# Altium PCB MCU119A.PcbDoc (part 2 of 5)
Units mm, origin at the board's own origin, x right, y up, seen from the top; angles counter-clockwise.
Board outline 58.62 x 144.37 mm, 6 copper layers (Top Signal, GND, Middle Signal, PWR, GND2, Bottom Signal), stack 1.566 mm thick; 316 components, 238 nets, 1210 pads, 1064 vias.
Unrouted connection lines stored in the file: 59.
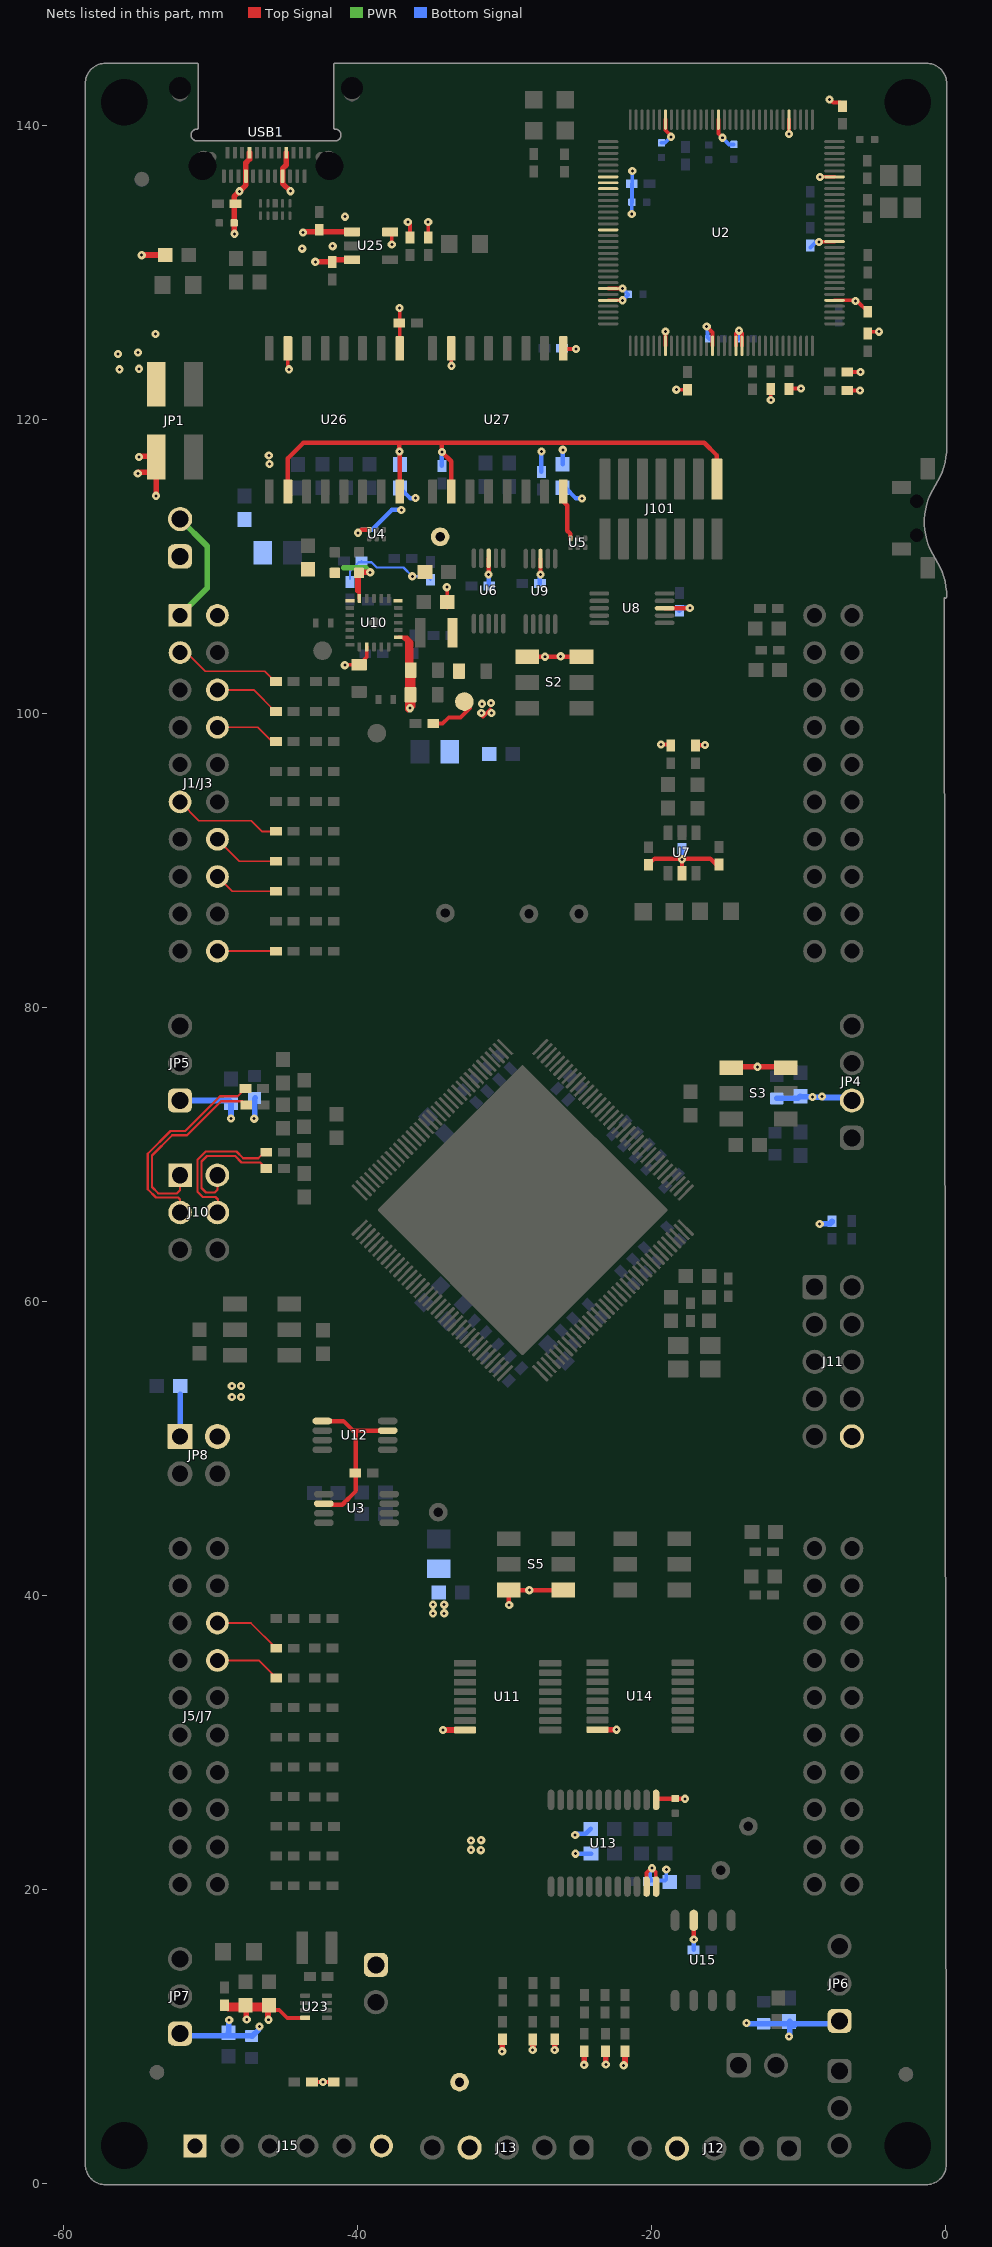
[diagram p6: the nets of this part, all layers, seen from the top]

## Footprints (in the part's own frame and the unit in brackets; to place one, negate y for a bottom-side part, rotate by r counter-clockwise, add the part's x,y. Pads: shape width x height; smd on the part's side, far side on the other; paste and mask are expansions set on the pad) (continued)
PDT0128A [mm] "Thin QFP, 128-Leads, Body 14x14mm, Pitch 0.4mm"
  oval 1.4x0.2 smd: 1(-7.7,6.2) 2(-7.7,5.8) 3(-7.7,5.4) 4(-7.7,5) 5(-7.7,4.6) 6(-7.7,4.2) 7(-7.7,3.8) 8(-7.7,3.4) 9(-7.7,3) 10(-7.7,2.6) 11(-7.7,2.2) 12(-7.7,1.8) 13(-7.7,1.4) 14(-7.7,1) 15(-7.7,0.6) 16(-7.7,0.2) 17(-7.7,-0.2) 18(-7.7,-0.6) 19(-7.7,-1) 20(-7.7,-1.4) 21(-7.7,-1.8) 22(-7.7,-2.2) 23(-7.7,-2.6) 24(-7.7,-3) 25(-7.7,-3.4) 26(-7.7,-3.8) 27(-7.7,-4.2) 28(-7.7,-4.6) 29(-7.7,-5) 30(-7.7,-5.4) 31(-7.7,-5.8) 32(-7.7,-6.2) 65(7.7,-6.2) 66(7.7,-5.8) 67(7.7,-5.4) 68(7.7,-5) 69(7.7,-4.6) 70(7.7,-4.2) 71(7.7,-3.8) 72(7.7,-3.4) 73(7.7,-3) 74(7.7,-2.6) 75(7.7,-2.2) 76(7.7,-1.8) 77(7.7,-1.4) 78(7.7,-1) 79(7.7,-0.6) 80(7.7,-0.2) 81(7.7,0.2) 82(7.7,0.6) 83(7.7,1) 84(7.7,1.4) 85(7.7,1.8) 86(7.7,2.2) 87(7.7,2.6) 88(7.7,3) 89(7.7,3.4) 90(7.7,3.8) 91(7.7,4.2) 92(7.7,4.6) 93(7.7,5) 94(7.7,5.4) 95(7.7,5.8) 96(7.7,6.2)
  oval 0.2x1.4 smd: 33(-6.2,-7.7) 34(-5.8,-7.7) 35(-5.4,-7.7) 36(-5,-7.7) 37(-4.6,-7.7) 38(-4.2,-7.7) 39(-3.8,-7.7) 40(-3.4,-7.7) 41(-3,-7.7) 42(-2.6,-7.7) 43(-2.2,-7.7) 44(-1.8,-7.7) 45(-1.4,-7.7) 46(-1,-7.7) 47(-0.6,-7.7) 48(-0.2,-7.7) 49(0.2,-7.7) 50(0.6,-7.7) 51(1,-7.7) 52(1.4,-7.7) 53(1.8,-7.7) 54(2.2,-7.7) 55(2.6,-7.7) 56(3,-7.7) 57(3.4,-7.7) 58(3.8,-7.7) 59(4.2,-7.7) 60(4.6,-7.7) 61(5,-7.7) 62(5.4,-7.7) 63(5.8,-7.7) 64(6.2,-7.7) 97(6.2,7.7) 98(5.8,7.7) 99(5.4,7.7) 100(5,7.7) 101(4.6,7.7) 102(4.2,7.7) 103(3.8,7.7) 104(3.4,7.7) 105(3,7.7) 106(2.6,7.7) 107(2.2,7.7) 108(1.8,7.7) 109(1.4,7.7) 110(1,7.7) 111(0.6,7.7) 112(0.2,7.7) 113(-0.2,7.7) 114(-0.6,7.7) 115(-1,7.7) 116(-1.4,7.7) 117(-1.8,7.7) 118(-2.2,7.7) 119(-2.6,7.7) 120(-3,7.7) 121(-3.4,7.7) 122(-3.8,7.7) 123(-4.2,7.7) 124(-4.6,7.7) 125(-5,7.7) 126(-5.4,7.7) 127(-5.8,7.7) 128(-6.2,7.7)
  silkscreen extent -7.7,-6.3 6.3,6.99, body extent -8,-8 8,8, height 1.07
PW0016A-MFG [mm]
  rrect22% 1.5x0.45 smd: 1(-2.9,2.275) 2(-2.9,1.625) 3(-2.9,0.975) 4(-2.9,0.325) 5(-2.9,-0.325) 6(-2.9,-0.975) 7(-2.9,-1.625) 8(-2.9,-2.275) 9(2.9,-2.275) 10(2.9,-1.625) 11(2.9,-0.975) 12(2.9,-0.325) 13(2.9,0.325) 14(2.9,0.975) 15(2.9,1.625) 16(2.9,2.275)
  silkscreen extent -4.38,-2.55 1.78,2.55, body extent -3.75,-2.8 3.75,2.8, height 0.25
PW0024A_N [mm] "TSOP, 24-Leads, Body 7.8x4.4mm, Pitch 0.65mm, IPC Medium Density"
  oval 1.4x0.45 smd: 1(-2.95,3.575) 2(-2.95,2.925) 3(-2.95,2.275) 4(-2.95,1.625) 5(-2.95,0.975) 6(-2.95,0.325) 7(-2.95,-0.325) 8(-2.95,-0.975) 9(-2.95,-1.625) 10(-2.95,-2.275) 11(-2.95,-2.925) 12(-2.95,-3.575) 13(2.95,-3.575) 14(2.95,-2.925) 15(2.95,-2.275) 16(2.95,-1.625) 17(2.95,-0.975) 18(2.95,-0.325) 19(2.95,0.325) 20(2.95,0.975) 21(2.95,1.625) 22(2.95,2.275) 23(2.95,2.925) 24(2.95,3.575)
  silkscreen extent -3.51,-3.95 1.6,4.04, body extent -3.21,-3.9 3.21,3.9, height 1
RAY0024B-MFG [mm]
  rrect40% 0.625x0.25 smd paste+0 mask+0: 1(-1.637,1.5) 7(-1.637,-1.5) 13(1.637,-1.5) 19(1.637,1.5)
  rrect40% 0.6x0.25 smd paste+0 mask+0: 2(-1.65,1) 3(-1.65,0.5) 5(-1.65,-0.5) 6(-1.65,-1) 14(1.65,-1) 15(1.65,-0.5) 17(1.65,0.5) 18(1.65,1)
  rrect40% 0.6x0.25 smd paste+0 mask-1000: 4(-1.65,0) 16(1.65,0)
  rrect40% 0.25x0.6 smd paste+0 mask+0: 8(-1,-1.65) 9(-0.5,-1.65) 10(0,-1.65) 11(0.5,-1.65) 12(1,-1.65) 20(1,1.65) 21(0.5,1.65) 22(0,1.65) 23(-0.5,1.65) 24(-1,1.65)
  round 0.777 smd paste-1000 mask+0: ""(0.037,-0.003)
  Top Signal region: -1.95,0.075 -1.943,0.1 -1.925,0.118 -1.9,0.125 -1.9,0.125 -1.4,0.125 -1.378,0.12 -1.361,0.106 -1.361,0.106 -1.344,0.092 -1.322,0.088 -1.322,0.088 -0.426,0.088 -0.406,0.091 -0.39,0.102 -0.379,0.118 -0.375,0.138 -0.376,0.138 -0.376,0.601 -0.369,0.626 -0.35,0.644 -0.325,0.651 -0.325,0.651 0.455,0.651 0.48,0.644 0.499,0.626 0.505,0.601 0.505,0.601 0.506,0.1 0.509,0.081 0.52,0.065 0.536,0.054 0.556,0.05 0.556,0.05 1.303,0.05 1.324,0.055 1.342,0.068 1.352,0.088 1.352,0.088 1.362,0.107 1.379,0.12 1.4,0.125 1.4,0.125 1.9,0.125 1.925,0.118 1.943,0.1 1.95,0.075 1.95,0.075 1.95,-0.075 1.943,-0.1 1.925,-0.118 1.9,-0.125 1.9,-0.125 0.556,-0.125 0.536,-0.129 0.52,-0.14 0.509,-0.156 0.506,-0.175 0.506,-0.175 0.506,-0.601 0.499,-0.626 0.481,-0.644 0.456,-0.651 0.455,-0.651 -0.326,-0.651 -0.35,-0.644 -0.369,-0.626 -0.375,-0.601 -0.375,-0.601 -0.376,-0.137 -0.379,-0.118 -0.39,-0.102 -0.406,-0.091 -0.425,-0.087 -0.426,-0.087 -1.322,-0.087 -1.344,-0.092 -1.361,-0.106 -1.361,-0.106 -1.378,-0.12 -1.4,-0.125 -1.4,-0.125 -1.9,-0.125 -1.925,-0.118 -1.943,-0.1 -1.95,-0.075 -1.95,-0.075
  silkscreen extent -2.62,-2.17 2.18,2.18, body extent -1.75,-1.75 1.75,1.75, height 1
RFS0144A-MFG [mm]
  rrect50% 1.45x0.2 smd paste+0 mask+0: 1(-8.7,7) 2(-8.7,6.6) 3(-8.7,6.2) 4(-8.7,5.8) 5(-8.7,5.4) 6(-8.7,5) 7(-8.7,4.6) 8(-8.7,4.2) 9(-8.7,3.8) 10(-8.7,3.4) 11(-8.7,3) 12(-8.7,2.6) 13(-8.7,2.2) 14(-8.7,1.8) 15(-8.7,1.4) 16(-8.7,1) 17(-8.7,0.6) 18(-8.7,0.2) 19(-8.7,-0.2) 20(-8.7,-0.6) 21(-8.7,-1) 22(-8.7,-1.4) 23(-8.7,-1.8) 24(-8.7,-2.2) 25(-8.7,-2.6) 26(-8.7,-3) 27(-8.7,-3.4) 28(-8.7,-3.8) 29(-8.7,-4.2) 30(-8.7,-4.6) 31(-8.7,-5) 32(-8.7,-5.4) 33(-8.7,-5.8) 34(-8.7,-6.2) 35(-8.7,-6.6) 36(-8.7,-7) 73(8.7,-7) 74(8.7,-6.6) 75(8.7,-6.2) 76(8.7,-5.8) 77(8.7,-5.4) 78(8.7,-5) 79(8.7,-4.6) 80(8.7,-4.2) 81(8.7,-3.8) 82(8.7,-3.4) 83(8.7,-3) 84(8.7,-2.6) 85(8.7,-2.2) 86(8.7,-1.8) 87(8.7,-1.4) 88(8.7,-1) 89(8.7,-0.6) 90(8.7,-0.2) 91(8.7,0.2) 92(8.7,0.6) 93(8.7,1) 94(8.7,1.4) 95(8.7,1.8) 96(8.7,2.2) 97(8.7,2.6) 98(8.7,3) 99(8.7,3.4) 100(8.7,3.8) 101(8.7,4.2) 102(8.7,4.6) 103(8.7,5) 104(8.7,5.4) 105(8.7,5.8) 106(8.7,6.2) 107(8.7,6.6) 108(8.7,7)
  rrect50% 0.2x1.45 smd paste+0 mask+0: 37(-7,-8.7) 38(-6.6,-8.7) 39(-6.2,-8.7) 40(-5.8,-8.7) 41(-5.4,-8.7) 42(-5,-8.7) 43(-4.6,-8.7) 44(-4.2,-8.7) 45(-3.8,-8.7) 46(-3.4,-8.7) 47(-3,-8.7) 48(-2.6,-8.7) 49(-2.2,-8.7) 50(-1.8,-8.7) 51(-1.4,-8.7) 52(-1,-8.7) 53(-0.6,-8.7) 54(-0.2,-8.7) 55(0.2,-8.7) 56(0.6,-8.7) 57(1,-8.7) 58(1.4,-8.7) 59(1.8,-8.7) 60(2.2,-8.7) 61(2.6,-8.7) 62(3,-8.7) 63(3.4,-8.7) 64(3.8,-8.7) 65(4.2,-8.7) 66(4.6,-8.7) 67(5,-8.7) 68(5.4,-8.7) 69(5.8,-8.7) 70(6.2,-8.7) 71(6.6,-8.7) 72(7,-8.7) 109(7,8.7) 110(6.6,8.7) 111(6.2,8.7) 112(5.8,8.7) 113(5.4,8.7) 114(5,8.7) 115(4.6,8.7) 116(4.2,8.7) 117(3.8,8.7) 118(3.4,8.7) 119(3,8.7) 120(2.6,8.7) 121(2.2,8.7) 122(1.8,8.7) 123(1.4,8.7) 124(1,8.7) 125(0.6,8.7) 126(0.2,8.7) 127(-0.2,8.7) 128(-0.6,8.7) 129(-1,8.7) 130(-1.4,8.7) 131(-1.8,8.7) 132(-2.2,8.7) 133(-2.6,8.7) 134(-3,8.7) 135(-3.4,8.7) 136(-3.8,8.7) 137(-4.2,8.7) 138(-4.6,8.7) 139(-5,8.7) 140(-5.4,8.7) 141(-5.8,8.7) 142(-6.2,8.7) 143(-6.6,8.7) 144(-7,8.7)
  rrect1% 14x14 smd paste-1000 mask-1000: 145(0,0)
  silkscreen extent -8.82,-8.05 8.05,8.05, body extent -9.53,-9.53 9.53,9.53, height 0.25
Samtec_TSM-102-01-x-DV [mm] "Header, 2.54mm, 2x2, SMT"
  rect 3.048x1.27 smd: 1(-2.475,-1.27) 2(2.475,-1.27) 3(-2.475,1.27) 4(2.475,1.27)
  silkscreen extent -1.75,-2.63 1.65,2.54, body extent -3.85,-2.54 3.85,2.54, height 9.65
SW_1188E [mm] "SMD, 4-Leads, Body 7.8x3.5mm"
  rrect10% 1x1.45 smd: 1(-1.1,3.375) 2(-1.1,-3.375)
  rrect11% 1.3x0.9 smd: 3(0.7,2.1) 4(0.7,-2.1)
  round 0 hole 0.9 unplated: ""(-0.35,1.15) ""(-0.35,-1.15)
  silkscreen extent -1.98,-2.28 0.95,2.28, body extent -2.55,-3.9 1.05,3.9, height 3.5
SW_CAS-220TA [mm] "COPAL ELECTRONICS"
  rect 1.6x1 smd: 1(-1.85,1.75) 2(-1.85,0) 3(-1.85,-1.75) 4(1.85,1.75) 5(1.85,0) 6(1.85,-1.75)
  silkscreen extent -2.11,-2.9 2,3.58, body extent -2.1,-2.85 2.1,2.85, height 2.51
SW_CAS-D20TA [mm] "SMD, 6-Leads, Body 5.4x3.9mm, Pitch 1.75mm"
  rect 1.6x1 smd: 1(-1.85,1.75) 2(-1.85,0) 3(-1.85,-1.75) 4(1.85,1.75) 5(1.85,0) 6(1.85,-1.75)
  silkscreen extent -1.95,-2.7 1.95,2.9, body extent -2.1,-2.7 2.1,2.7, height 2.5
TFM252012 [mm] "SMD, 2-Leads, Body 2.5x2mm"
  rect 0.7x2 smd: 1(-1.1,0) 2(1.1,0)
  silkscreen extent -0.45,-1.1 0.45,1.1, body extent -1.35,-1.1 1.35,1.1, height 1.2
TI_Stacked_Overlay_Medium [mm]
  silkscreen extent -14.62,-3.44 14.62,3.42
TI_Symbol_Overlay_Small [mm]
  silkscreen extent -2.3,-2.23 2.3,2.24
TP_50MIL-25MILHOLE#1 [mm]
  round 1.27 hole 0.635: 1(0,0)
TP_50MIL-25MILHOLE#2 [mm]
  round 1.27 smd paste-2: 1(0,0)
TP_50MIL-25MILHOLE#3 [mm]
  round 1.27 smd paste-5.08: 1(0,0)
WEEE_Minimum [mm] "WEEElie bin"
  silkscreen extent -2.42,-4.38 2.52,2.65
WL-SMCW_Green_0805 [mm] "SMD, 2-Leads, Body 2x1.25mm"
  rect 1.1x1.2 smd: 1(-1.05,0) 2(1.05,0)
  silkscreen extent -2.39,-1.1 1.5,1.1, body extent -1,-0.62 1,0.63, height 0.7
WL-SMCW_RED_0805 [mm] "SMD, 2-Leads, Body 1.6x0.8mm"
  rect 1.1x1.2 smd: 1(-1.05,0) 2(1.05,0)
  silkscreen extent -2.4,-1.1 1.5,1.1, body extent -1,-0.62 1,0.63, height 0.7
Wurth_60900213421 [mil] "Shunt, 2.54mm, Black"
  round 1 on Mech3: 0(0,0)
  body extent -98,-48 98,48, height 338
WURTH_61300211121 [mm] "Header, 2.54mm, 2x1, TH"
  rrect50% 1.65x1.65 hole 1.15: 1(-1.27,0)
  round 1.65 hole 1.15: 2(1.27,0)
  body extent -2.54,-1.27 2.54,1.27, height 8.54
WURTH_61300311121 [mm] "Header, 2.54mm, 3x1, TH"
  rrect50% 1.65x1.65 hole 1.15: 1(-2.54,0)
  round 1.65 hole 1.15: 2(0,0) 3(2.54,0)
  body extent -3.81,-1.27 3.81,1.27, height 8.54
WURTH_61300411121 [mm] "Header, 2.54mm, 4x1, TH"
  rrect50% 1.65x1.65 hole 1.15: 1(-3.81,0)
  round 1.65 hole 1.15: 2(-1.27,0) 3(1.27,0) 4(3.81,0)
  body extent -5.08,-1.27 5.08,1.27, height 8.54
Wurth_61300511121 [mm] "Header, 2.54mm, 5x1, TH"
  rrect50% 1.65x1.65 hole 1.1: 1(-5.08,0)
  round 1.65 hole 1.1: 2(-2.54,0) 3(0,0) 4(2.54,0) 5(5.08,0)
  body extent -6.35,-1.27 6.35,1.27, height 8.54
Wurth_61300621121 [mm] "Header, 2.54mm, 3x2, TH"
  rect 1.6x1.6 hole 1.1: 1(-1.27,2.54)
  round 1.6 hole 1.1: 2(1.27,2.54) 3(-1.27,0) 4(1.27,0) 5(-1.27,-2.54) 6(1.27,-2.54)
  silkscreen extent -2.8,-3.82 2.54,3.8, body extent -2.54,-3.82 2.54,3.8, height 7.27
WURTH_61301021121 [mm] "Header, 2.54mm, 5x2, TH"
  rrect25% 1.65x1.65 hole 1.15: 1(-5.08,-1.27)
  round 1.65 hole 1.15: 2(-5.08,1.27) 3(-2.54,-1.27) 4(-2.54,1.27) 5(0,-1.27) 6(0,1.27) 7(2.54,-1.27) 8(2.54,1.27) 9(5.08,-1.27) 10(5.08,1.27)
  silkscreen extent -6.35,-2.9 6.35,2.54, body extent -6.35,-2.54 6.35,2.54, height 8.54

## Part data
C1 C2 C3 C4 C5 C12 C16 C17 C18 C55 C56 C57 C58 C63 C66 C67 C68 C69 C70 C71 C72 C73 C97 C98 C99 C100 C101 C102 C103 C104 C105 C106 C128 C129 C130 C132 C133: library part CMP-0006228-2, "CAP, CERM, 0.1 uF, 16 V, +/- 10%, X7R, 0402", Cap_Case=0402, Manufacturer="Wurth Elektronik", Supplier Part Number 1=732-7532-1-ND, TempCo=X7R, Tolerance_%=10%, Value1=Unknown, Value2=16V, ValueDisplayed=0.1uF
C6 C7 C8 C9 C10 C11 C23: library part CMP-0006231-2, "CAP, CERM, 1000 pF, 50 V, +/- 10%, X7R, 0402", Cap_Case=0402, Manufacturer="Wurth Elektronik", Supplier Part Number 1=732-7556-1-ND, TempCo=X7R, Tolerance_%=10%, Value1=Unknown, Value2=50V, ValueDisplayed=1000pF
C13 C14: library part CMP-0007341-5, "CAP, CERM, 4.7 uF, 16 V, +/- 10%, X5R, 0603", Cap_Case=0603, Manufacturer=MuRata, PartNumber=GRM188R61C475KAAJ, Supplier Part Number 1=490-10481-1-ND, TempCo=X5R, Tolerance_%=10%, Value1=Unknown, Value2=16V, ValueDisplayed=2.2uF
C15 C126 C127: library part CMP-0078623-1, "CAP, CERM, 10 ¦ÌF, 10 V,+/- 20%, X5R, 0402", Cap_Case=0402_080, Manufacturer=AVX, Supplier Part Number 1=478-10052-1-ND, TempCo=X5R, Tolerance_%=20%, Value2=10V, ValueDisplayed=10¦ÌF
C19 C20: library part CMP-0006239-2, "CAP, CERM, 12 pF, 25 V, +/- 5%, C0G/NP0, AEC-Q200 Grade 1, 0402", Cap_Case=0402, Manufacturer=Kemet, Supplier Part Number 1=399-6829-1-ND, TempCo=C0G/NP0, Tolerance_%=5%, Value1=Unknown, Value2=25V, ValueDisplayed=12pF
C21 C137 C138 C143 C145: library part CMP-0090362-1, "0.1¦ÌF ¡À10% 10V Ceramic Capacitor X7R 0402 (1005 Metric)", Digikey Part Number=732-7513-1-ND, Manufacturer="Wurth Electronics", Mouser Part Number=710-885012205018, Operating Temperature Range="-55¡ãC to +125¡ãC", TempCo=15%, Temperature Characteristic=X7R, Tolerance_%=10%, ValueDisplayed=100000pF
C22 C51 C75 C77 C79 C82 C84 C88 C91: library part CMP-0006862-5, "CAP, CERM, 0.1 uF, 10 V, +/- 10%, X7R, 0603", Cap_Case=0603, Manufacturer=Kemet, Supplier Part Number 1=399-1095-1-ND, TempCo=X7R, Tolerance_%=10%, Value1=Unknown, Value2=10V, ValueDisplayed=0.1uF
C24 C25: library part CMP-0006920-4, "CAP, CERM, 1000 pF, 50 V, +/- 5%, C0G/NP0, 0603", Cap_Case=0603, Manufacturer=Kemet, PartNumber=C0603C331J5GACTU, Supplier Part Number 1=399-1068-1-ND, TempCo=C0G/NP0, Tolerance_%=5%, Value1=Unknown, Value2=50V, ValueDisplayed=330pF
C26 C27 C30 C31 C33 C34 C35 C36 C37 C38 C39 C40 C42 C43 C45 C46 C47 C48 C49 C50: library part CMP-0006456-2, "CAP, CERM, 330 pF, 50 V, +/- 5%, C0G/NP0, 0402", Cap_Case=0402, Manufacturer=MuRata, Supplier Part Number 1=490-1295-1-ND, TempCo=C0G/NP0, Tolerance_%=5%, Value1=Unknown, Value2=50V, ValueDisplayed=330pF
C28: library part CMP-0123381-1, "Ceramic Capacitor for Automotive 200pF ¡À1% 50VDC C0G 0402 Paper T/R", Manufacturer=Murata, Operating Temperature Range="-55¡ãC to +125¡ãC", TempCo=30ppm/¡ãC, Temperature Characteristic=C0G, Tolerance_%=0.01%, ValueDisplayed=200pF
C29 C32 C41 C44: library part CMP-0006920-4, "CAP, CERM, 2200 pF, 50 V, +/- 5%, X7R, 0402", Cap_Case=0603, Manufacturer=Kemet, PartNumber=C0603C331J5GACTU, Supplier Part Number 1=399-1068-1-ND, TempCo=C0G/NP0, Tolerance_%=5%, Value1=Unknown, Value2=50V, ValueDisplayed=330pF
C52: library part CMP-0006871-4, "CAP, CERM, 1 uF, 6.3 V, +80/-20%, Y5V, 0603", Cap_Case=0603, Manufacturer=Kemet, Supplier Part Number 1=399-3217-1-ND, TempCo=Y5V, Tolerance_%=80%, Value1=Unknown, Value2=6.3V, ValueDisplayed=1uF
C53: library part CMP-0006907-5, "CAP, CERM, 2.2 uF, 6.3 V, +/- 10%, X5R, 0603", Cap_Case=0603, Manufacturer=Kemet, Supplier Part Number 1=399-3362-1-ND, TempCo=X5R, Tolerance_%=10%, Value1=Unknown, Value2=6.3V, ValueDisplayed=2.2uF
C54 C59: library part CMP-0086225-1, "CAP, CERM, 10 ¦ÌF, 16 V,+/- 10%, X5R, 0603", Cap_Case=0603, Manufacturer=MuRata, Supplier Part Number 1=490-10728-1-ND, TempCo=X5R, Tolerance_%=10%, Value2=16V, ValueDisplayed=10¦ÌF
C60 C61 C62 C64 C65: library part CMP-0006825-5, "CAP, CERM, 2.2 uF, 16 V, +/- 20%, X5R, 0603", Cap_Case=0603, Manufacturer="Wurth Elektronik", Supplier Part Number 1=732-7915-1-ND, TempCo=X5R, Tolerance_%=20%, Value1=Unknown, Value2=16V, ValueDisplayed=2.2uF
C74 C76 C78 C81 C83: library part CMP-0092309-1, "Cap Ceramic 10uF 10V X5R 10% SMD 0603 85C Paper T/R", Digikey Part Number=311-1782-1-ND, Manufacturer=YAGEO, Mouser Part Number=603-CC603KRX5R6BB106, Octopart Part Number=1f0ad7d7c223c0cd, Operating Temperature Range="-55¡ãC to +85¡ãC", TempCo=15%, Temperature Characteristic=X5R, Tolerance_%=10%, ValueDisplayed=10uF
C80: library part CMP-0092424-1, "Cap Cer 3300pF 50V X7R 0402", Digikey Part Number=732-7559-1-ND, Manufacturer="Wurth Electronics", Mouser Part Number=710-885012205064, Operating Temperature Range="-55¡ãC to +125¡ãC", TempCo=15%, Temperature Characteristic=X7R, Tolerance_%=10%, ValueDisplayed=3.3nF
C85 C92 C93 C94: library part CMP-0089543-1, "10¦ÌF ¡À10% 10V Ceramic Capacitor X7S 0805 (2012 Metric)", Digikey Part Number=445-173805-1-ND, Manufacturer=TDK, Mouser Part Number=810-CG4J3X7S1A106KAE, Operating Temperature Range="-55¡ãC to +125¡ãC", TempCo=22%, Temperature Characteristic=X7S, Tolerance_%=10%, ValueDisplayed=10uF
C86 C87: library part CMP-0094207-1, "Cap Ceramic 2.2uF 10V X7S 10% Pad SMD 0603 +125¡ãC Automotive T/R", Manufacturer=TDK, Operating Temperature Range="-55¡ãC to +125¡ãC", TempCo=0.22, Temperature Characteristic=X7S, Tolerance_%=0.1%, ValueDisplayed=2.2uF
C89 C90: library part CMP-0006349-2, "CAP, CERM, 1 uF, 10 V, +/- 10%, X7S, AEC-Q200 Grade 1, 0402", Cap_Case=0402, Manufacturer=MuRata, Supplier Part Number 1=81-GCM155C71A105KE8D, TempCo=X7S, Tolerance_%=10%, Value1=Unknown, Value2=10V, ValueDisplayed=1uF
C107 C120 C121: library part CMP-0007324-5, "CAP, CERM, 22 uF, 10 V, +/- 20%, X5R, 0603", Cap_Case=0603, Manufacturer=MuRata, Supplier Part Number 1=490-10476-1-ND, TempCo=X5R, Tolerance_%=20%, Value1=Unknown, Value2=10V, ValueDisplayed=22uF
C119: library part CMP-0007341-5, "CAP, CERM, 4.7 uF, 16 V, +/- 10%, X5R, 0603", Cap_Case=0603, Manufacturer=MuRata, Supplier Part Number 1=490-10481-1-ND, TempCo=X5R, Tolerance_%=10%, Value1=Unknown, Value2=16V, ValueDisplayed=4.7uF
C131 C134 C135 C136 C141: library part CMP-0090363-1, "10000pF ¡À10% 25V Ceramic Capacitor X7R 0402 (1005 Metric)", Digikey Part Number=732-7545-1-ND, Manufacturer="Wurth Electronics", Mouser Part Number=710-885012205050, Operating Temperature Range="-55¡ãC to +125¡ãC", TempCo=15%, Temperature Characteristic=X7R, Tolerance_%=10%, ValueDisplayed=10000pF
C139 C140 C142 C144: library part CMP-0064924-2, "CAP, CERM, 1 uF, 10 V,+/- 20%, X5R, 0402", Cap_Case=0402, Manufacturer="Wurth Elektronik", Supplier Part Number 1=732-7489-1-ND, TempCo=X5R, Tolerance_%=20%, Value1=Unknown, Value2=10V, ValueDisplayed=1uF
C146 C147: library part CMP-0006345-2, "CAP, CERM, 12 pF, 50 V, +/- 5%, C0G/NP0, 0402", Cap_Case=0402, Manufacturer="Samsung Electro-Mechanics", Supplier Part Number 1=1276-1178-1-ND, TempCo=C0G/NP0, Tolerance_%=5%, Value1=Unknown, Value2=50V, ValueDisplayed=12pF
"CE Logo1": library part CMP-0074844-2, Manufacturer="Texas Instruments"
FID1 FID2 FID3 FID4 FID5 FID6: library part CMP-0077181-1, "Fiducial mark.  There is nothing to buy or mount.", Manufacturer=N/A
J1/J3: library part CMP-0003837-4, "Receptacle, 2.54mm, 10x2, Tin, TH", Alternate Manufacturer="Major League Electronics", Alternate PartNumber=CRD-081413-A-G, Manufacturer=Samtec, Supplier Part Number 1=SAM1204-10-ND
J4/J2: library part CMP-0078266-4, "Receptacle, 2.54mm, 10x2, Tin, TH", Alternate Manufacturer="Major League Electronics", Alternate PartNumber=CRD-081413-A-G, Manufacturer=Samtec, Supplier Part Number 1=SAM1204-10-ND
J5/J7: library part CMP-0081070-3, "Receptacle, 2.54mm, 10x2, Tin, TH", Alternate Manufacturer="Major League Electronics", Alternate PartNumber=CRD-081413-A-G, Manufacturer=Samtec, Supplier Part Number 1=SAM1204-10-ND
J8/J6: library part CMP-0081071-3, "Receptacle, 2.54mm, 10x2, Tin, TH", Alternate Manufacturer="Major League Electronics", Alternate PartNumber=CRD-081413-A-G, Manufacturer=Samtec, Supplier Part Number 1=SAM1204-10-ND
J10: library part CMP-0054802-2, "Header, 2.54mm, 3x2, Gold, TH", Color=Black, Manufacturer="Wurth Elektronik", Supplier Part Number 1=732-5295-ND
J11: library part CMP-0054806-3, "Header, 2.54 mm, 5x2, Gold, TH", Current_A=3A, Manufacturer="Wurth Elektronik", Supplier Part Number 1=732-2672-ND, Voltage_V=250V
J12 J13: library part CMP-0084909-1, "Header, 2.54mm, 5x1, Gold, TH", Color=Black, Current_A=3A, Manufacturer="Wurth Elektronik", Voltage_V=250V
J14 JP5 JP6 JP7: library part CMP-0054796-4, "Header, 2.54 mm, 3x1, Gold, TH", Manufacturer="Wurth Elektronik", Supplier Part Number 1=732-5316-ND
J15: library part CMP-0095629-2, "Connector Header Through Hole 6 position 0.100\" (2.54mm)", Current_A=6.3A, Digikey Part Number=SAM10539-ND, Manufacturer=Samtec, Mouser Part Number=200-HTSW10607GS, Operating Temperature Range="-55¡ãC to +125¡ãC", Voltage_V=550V
J17 J18 JP9: library part CMP-0054794-2, "Header, 2.54 mm, 2x1, Gold, TH", Color=Black, Manufacturer="Wurth Elektronik", Supplier Part Number 1=732-5315-ND
J101: library part CMP-0092335-1, "Connector, Header, Dual Row, 14 pin, .05\" pitch/row spacing, Male, Shrouded, Keyed, IDC, SMT", Current_A=3.4A, Digikey Part Number=612-FTSH-107-01-F-DV-K-ND, Manufacturer=Samtec, Mouser Part Number=200-FTSH10701FDVK, Octopart Part Number=b9dd70752dfc661a, Operating Temperature Range="-55¡ãC to +125¡ãC"
JP1: library part CMP-0055559-1, "Header, 2.54mm, 2x2, Gold, SMT", Color=Black, Manufacturer=Samtec, Supplier Part Number 1=TSM-102-01-L-DV-ND, Voltage_V=475V
JP4: library part CMP-0054798-2, "Header, 2.54 mm, 4x1, Gold, TH", Color=Black, Manufacturer="Wurth Elektronik", Supplier Part Number 1=732-5317-ND
JP8: library part CMP-0092422-1, "THT Vertical Pin Header WR-PHD, Pitch 2.54 mm, Dual Row, 4 pins", Current_A=3A, Digikey Part Number=732-5294-ND, Manufacturer="Wurth Electronics", Mouser Part Number=710-61300421121, Operating Temperature Range="-40¡ãC to +105¡ãC", Voltage_V=250V
L1: library part CMP-0003363-1, "Ferrite Bead, 220 ohm @ 100 MHz, 2 A, 0805", Manufacturer=MuRata, Supplier Part Number 1=490-1054-1-ND, Value1="0.045 ohm", Value2=2A, ValueDisplayed="220 ohm"
L2 L3: library part CMP-0003093-1, "Ferrite Bead, 60 ohm @ 100 MHz, 3 A, 0805", Manufacturer="Wurth Elektronik", PartNumber=742792063, Supplier Part Number 1=732-1612-1-ND, Value1="0.025 ohm", Value2=3A
L4: library part CMP-0063237-1, "Inductor, Shielded, 470 nH, 4 A, 0.026 ohm, SMD", Manufacturer=Vishay-Dale, Supplier Part Number 1=541-2674-1-ND, Value1="0.026 ohm", Value2=4A, ValueDisplayed=470nH
L5: library part CMP-0062879-1, "Inductor, Film, 1 uH, 3.7 A, 0.042 ohm, AEC-Q200 Grade 0, SMD", Manufacturer=TDK, Value1="0.042 ohm", Value2=3.7A, ValueDisplayed=1uH
LED1 LED4 LED7: library part CMP-0002951-3, "LED, Red, SMD", Color=Red, Manufacturer="Wurth Elektronik", Power_TotalModule=72mW, Value1=0.072W, Value2=1.9V
LED3: library part CMP-0002960-2, "LED, Bright Green, SMD", Color="Bright Green", Manufacturer="Wurth Elektronik", Power_TotalModule=72mW, Supplier Part Number 1=732-4986-1-ND, Value1=0.072W, Value2=2V
LED5: library part CMP-0002830-3, "LED, Green, SMD", Color=green, Manufacturer=Lite-On, Value1=W, Value2=2.1V
LED8 LED9: library part CMP-0002889-2, "LED, Blue, SMD", Color=Blue, Manufacturer=Lite-On, Value1=W, Value2=3.3V
Logo1 Logo5: library part CMP-0074838-1, "Texas Instrument Corporate Signature"
Logo3: library part CMP-0074847-1, "FCC_disclaimer"
Logo4: library part CMP-0074769-4, Manufacturer="Texas Instruments"
Logo6: library part CMP-0084011-3, "EtherCAT logo"
M1 M2 M3 M4 M6 M7: library part CMP-0003761-2, "Shunt, 2.54mm, Gold, Black", Manufacturer="Wurth Elektronik", Supplier Part Number 1=732-2678-ND
MH1 MH2 MH3 MH4: library part CMP-0078424-2, "PCB Mounting Hole, No Pad", Manufacturer=Any, PartNumber=N/A
R1 R2 R3 R4 R74 R76 R97 R98 R99 R100 R165 R171: library part CMP-0025874-4, "RES, 0, 5%, 0.1 W, AEC-Q200 Grade 0, 0603", Manufacturer=Panasonic, Power_W=100mW, Supplier Part Number 1=P0.0GCT-ND, TempCo="600 ppm/C", Tolerance_%=5%, Value2=0.1W, Value_Code=0000, ValueDisplayed=0
R5 R6 R7 R8 R9 R10 R101 R102 R103 R104: library part CMP-0026071-3, "RES, 1.00 k, 1%, 0.063 W, AEC-Q200 Grade 0, 0402", Manufacturer=Vishay-Dale, Power_W=63mW, Supplier Part Number 1=541-1.00KLCT-ND, TempCo="100 ppm/C", Tolerance_%=1%, Value2=0.063W, Value_Code=1k00, ValueDisplayed=1.00k
R11: library part CMP-0022769-5, "RES, 120, 1%, 0.1 W, 0603", Manufacturer=Yageo, Power_W=100mW, Supplier Part Number 1=311-120HRCT-ND, TempCo="100 ppm/C", Tolerance_%=1%, Value2=0.1W, Value_Code=120R, ValueDisplayed=120
R12 R13 R96: library part CMP-0026962-3, "RES, 680, 5%, 0.063 W, AEC-Q200 Grade 0, 0402", Manufacturer=Vishay-Dale, Power_W=63mW, Supplier Part Number 1=541-680JCT-ND, TempCo="200 ppm/C", Tolerance_%=5%, Value2=0.063W, Value_Code=680R, ValueDisplayed=680
R14 R15: library part CMP-0026826-2, "RES, 10 M, 5%, 0.063 W, AEC-Q200 Grade 0, 0402", Manufacturer=Vishay-Dale, Power_W=63mW, Supplier Part Number 1=541-10MJCT-ND, TempCo="200 ppm/C", Tolerance_%=5%, Value2=0.063W, Value_Code=10M0, ValueDisplayed=10M
R16: library part CMP-0026918-5, "RES, 3.3 k, 5%, 0.063 W, AEC-Q200 Grade 0, 0402", Manufacturer=Vishay-Dale, Power_W=63mW, Supplier Part Number 1=541-3.3KJCT-ND, TempCo="200 ppm/C", Tolerance_%=5%, Value2=0.063W, Value_Code=3k30, ValueDisplayed=3.3k
R17 R19 R20 R21 R30 R35 R36: library part CMP-0025697-4, "RES, 0, 5%, 0.1 W, AEC-Q200 Grade 0, 0603", Manufacturer=Vishay-Dale, Power_W=100mW, Supplier Part Number 1=541-0.0GCT-ND, TempCo="200 ppm/C", Tolerance_%=5%, Value2=0.1W, Value_Code=0000, ValueDisplayed=0
R18 R44 R59: library part CMP-0026890-5, "RES, 2.2 k, 5%, 0.063 W, AEC-Q200 Grade 0, 0402", Manufacturer=Vishay-Dale, Power_W=63mW, Supplier Part Number 1=541-2.2KJCT-ND, TempCo="200 ppm/C", Tolerance_%=5%, Value2=0.063W, Value_Code=2k20, ValueDisplayed=2.2k
R22: library part CMP-0023387-3, "RES, 50, 0.1%, 0.125 W, 0603", Manufacturer="Vishay Thin Film", Power_W=125mW, Supplier Part Number 1=FC0603-50BFCT-ND, TempCo="25 ppm/C", Tolerance_%=0.1%, Value2=0.125W, Value_Code=50R0, ValueDisplayed=50
R23 R24: library part CMP-0026890-5, "RES, 10 k, 5%, 0.063 W, AEC-Q200 Grade 0, 0402", Manufacturer=Vishay-Dale, PartNumber=CRCW04022K20JNED, Power_W=63mW, Supplier Part Number 1=541-2.2KJCT-ND, TempCo="200 ppm/C", Tolerance_%=5%, Value2=0.063W, Value_Code=2k20, ValueDisplayed=10k
R25 R28: library part CMP-0026938-1, "RES, 4.7 k, 5%, 0.063 W, 0402", Manufacturer=Vishay-Dale, Power_W=63mW, Supplier Part Number 1=541-4.7KJCT-ND, TempCo="200 ppm/C", Tolerance_%=5%, Value2=0.063W, Value_Code=4k70, ValueDisplayed=4.7k
R26 R29 R32 R37 R38 R39 R40 R43 R45 R46 R47 R50 R51 R52 R53 R54 R55 R56 R57 R58 R60 R61 R62 R72 R107: library part CMP-0027004-2, "RES, 0, 5%, 0.063 W, 0402", Manufacturer="Yageo America", Power_W=63mW, Supplier Part Number 1=311-0.0JRCT-ND, TempCo="200 ppm/C", Tolerance_%=5%, Value2=0.063W, Value_Code=0000, ValueDisplayed=0
R27: library part CMP-0077731-1, "RES, 10.0 k, 1%, 0.063 W, AEC-Q200 Grade 0, 0402", Manufacturer="Yageo America", Power_W=63mW, Supplier Part Number 1=YAG3436CT-ND, TempCo="100 ppm/C", Tolerance_%=1%, Value2=0.063W, Value_Code=10k0, ValueDisplayed=10.0k
R31 R33: library part CMP-0022746-5, "RES, 10.0 k, 1%, 0.1 W, 0603", Manufacturer=Yageo, Power_W=100mW, Supplier Part Number 1=311-10.0KHRCT-ND, TempCo="100 ppm/C", Tolerance_%=1%, Value2=0.1W, Value_Code=10k0, ValueDisplayed=10.0k
R34: library part CMP-0025769-4, "RES, 2.2 k, 5%, 0.1 W, AEC-Q200 Grade 0, 0603", Manufacturer=Vishay-Dale, Power_W=100mW, Supplier Part Number 1=541-2.2KGCT-ND, TempCo="200 ppm/C", Tolerance_%=5%, Value2=0.1W, Value_Code=2k20, ValueDisplayed=2.2k
R41 R42 R48 R49: library part CMP-0027004-2, "RES, 33, 5%, 0.063 W, AEC-Q200 Grade 0, 0402", Manufacturer="Yageo America", PartNumber=RC0402JR-070RL, Power_W=63mW, Supplier Part Number 1=311-0.0JRCT-ND, TempCo="200 ppm/C", Tolerance_%=5%, Value2=0.063W, Value_Code=0000, ValueDisplayed=33
R68: library part CMP-0026100-2, "RES, 1.00 M, 1%, 0.063 W, AEC-Q200 Grade 0, 0402", Manufacturer=Vishay-Dale, Power_W=63mW, Supplier Part Number 1=541-1.00MLCT-ND, TempCo="100 ppm/C", Tolerance_%=1%, Value2=0.063W, Value_Code=1M00, ValueDisplayed=1.00M
R69: library part CMP-0025921-5, "RES, 3.0 k, 5%, 0.1 W, 0603", Manufacturer=Yageo, Power_W=100mW, Supplier Part Number 1=311-3.0KGRCT-ND, TempCo="100 ppm/C", Tolerance_%=5%, Value2=0.1W, Value_Code=3k00, ValueDisplayed=3.0k
R78 R81: library part CMP-0025932-5, "RES, 5.1 k, 5%, 0.1 W, 0603", Manufacturer=Yageo, Power_W=100mW, Supplier Part Number 1=311-5.1KGRCT-ND, TempCo="100 ppm/C", Tolerance_%=5%, Value2=0.1W, Value_Code=5k10, ValueDisplayed=5.1k
R82: library part CMP-0026853-5, "RES, 1.1 k, 5%, 0.063 W, AEC-Q200 Grade 0, 0402", Manufacturer=Vishay-Dale, Power_W=63mW, Supplier Part Number 1=541-1.1KJCT-ND, TempCo="200 ppm/C", Tolerance_%=5%, Value2=0.063W, Value_Code=1k10, ValueDisplayed=1.1k
R164: library part CMP-0026824-3, "RES, 100, 5%, 0.063 W, AEC-Q200 Grade 0, 0402", Manufacturer=Vishay-Dale, Power_W=63mW, Supplier Part Number 1=541-100JCT-ND, TempCo="200 ppm/C", Tolerance_%=5%, Value2=0.063W, Value_Code=100R, ValueDisplayed=100
R172 R173: library part CMP-0026736-1, "RES, 470, 1%, 0.063 W, 0402", Manufacturer="Yageo America", Power_W=63mW, Supplier Part Number 1=311-470LRCT-ND, TempCo="100 ppm/C", Tolerance_%=1%, Value2=0.063W, Value_Code=470R, ValueDisplayed=470
R174 R175: library part CMP-0026825-5, "RES, 10 k, 5%, 0.063 W, AEC-Q200 Grade 0, 0402", Manufacturer=Vishay-Dale, Power_W=63mW, Supplier Part Number 1=541-10KJCT-ND, TempCo="200 ppm/C", Tolerance_%=5%, Value2=0.063W, Value_Code=10k0, ValueDisplayed=10k
R176: library part CMP-0026413-2, "RES, 4.87 k, 1%, 0.063 W, AEC-Q200 Grade 0, 0402", Manufacturer=Vishay-Dale, Power_W=63mW, Supplier Part Number 1=541-4.87KLCT-ND, TempCo="100 ppm/C", Tolerance_%=1%, Value2=0.063W, Value_Code=4k87, ValueDisplayed=4.87k
R177: library part CMP-0026946-3, "RES, 51, 5%, 0.063 W, AEC-Q200 Grade 0, 0402", Manufacturer=Vishay-Dale, Power_W=63mW, Supplier Part Number 1=541-51JCT-ND, TempCo="200 ppm/C", Tolerance_%=5%, Value2=0.063W, Value_Code=51R0, ValueDisplayed=51
S1: library part CMP-0002328-1, "Switch, SPST, 0.05 A, 12 VDC, SMD", CurrentRating_mA=50A, Manufacturer=Diptronics
S2 S3 S5 S6: library part CMP-0002233-1, "Switch, Dual SPDT,  2 Pos, 0.1A, 6VDC, SMD", CurrentRating_mA=100A, Manufacturer="Copal Electronics", Supplier Part Number 1=CASD20JCT-ND
S4: library part CMP-0002123-2, "SLIDE SWITCH DPDT  .1A, SMT", CurrentRating_mA=100A, Manufacturer="Copal Electronics", Supplier Part Number 1=CAS220JCT-ND
TP1 TP2 TP3 TP4 TP5 TP6 TP7 TP8 TP9 TP10 TP11: library part CMP-0078143-4, "TEST POINT.  No entry in BOM.", Manufacturer=N/A
U1: library part CMP-0121584-3, "Real-Time Microcontroller, HTQFP144", Frequency_Fixed=200MHz, Manufacturer="Texas Instruments", Max Supply Voltage=3.63V, Min Supply Voltage=1.14V, Operating Temperature Range="-40¡ãC to +125¡ãC"
U2: library part CMP-0077953-1, "MSP432E401YTPDT, PDT0128A (TQFP-128)", Alternate Manufacturer="Texas Instruments", Alternate PartNumber=MSP432E401YTPDTR
U3: library part CMP-0032596-2, "Low Noise, Very Low Drift, Precision Series Voltage Reference, DGK0008A (VSSOP-8)", Manufacturer="Texas Instruments", Rating=Catalog, Temp Coeff(Max)(ppm/ degree C)=3
U4 U5: library part CMP-0043115-3, "4-Channel ESD Protection Array for High-Speed Data Interfaces, DRY0006A (USON-6)", Breakdown Voltage(Min)(V)=6, IO Capacitance(Typ)(pF)=1.6, IO Leakage Current(nA)=1, Manufacturer="Texas Instruments", Operating Temperature Range="-40 to 85 C", Rating=Catalog
U6 U8 U9: library part CMP-0067418-1, "DUAL 10-Ohm SPDT ANALOG SWITCH, DGS0010A (VSSOP-10)", Alternate Manufacturer="Texas Instruments", Alternate PartNumber=TS5A23157DGST
U7: library part CMP-0051789-2, "Dual Buffer/Driver with Open-Drain Output, DBV0006A, LARGE T&R", F @ Nom Voltage(Max)(Mhz)=150, Generic Part Number=SN74LVC2G07, ICC @ Nom Voltage(Max)(mA)=0.01, Manufacturer="Texas Instruments", Operating Temperature Range(C)="-40 to 125", Rating=Catalog, tpd @ Nom Voltage(Max)(ns)=8.6,4.4,3.7,2.9, Voltage(Nom)(V)=1.8,2.5,3.3,5
U10: library part CMP-0119993-1, "Automotive Camera PMIC", Manufacturer="Texas Instruments", Max Supply Voltage=35V, Min Supply Voltage=4V, Operating Temperature Range="-40¡ãC to +150¡ãC", Output Voltage=3-5.5/0.6-3.4/0.6-3.4/1.8-3.4V
U11 U14: library part CMP-0089841-1, "3 Circuit IC Switch 2:1 75Ohm 16-TSSOP", Digikey Part Number=296-3833-1-ND, Manufacturer="Texas Instruments", Max Supply Voltage=5.5V, Min Supply Voltage=2V, Mouser Part Number=595-SN74LV4053APWR, Nominal Supply Current=20uA, On State Resistance=100-225¦¸, Operating Temperature Range="-40¡ãC to +85¡ãC"
U12: library part CMP-0040679-2, "Precision, Zero-Crossover, 20MHz, 0.9pA Ib, RRIO, CMOS Operational Amplifier, DGK0008A (VSSOP-8)", Manufacturer="Texas Instruments", Total Supply Voltage(Max)(+5V is 5, +/-5V is 10)=5.5, Total Supply Voltage(Min)(+5V is 5, +/-5V is 10)=1.8
U13: library part CMP-0066458-2, "8-Bit Dual-Supply Bus Transceiver with Configurable Voltage-Level Shifting and Three-State Outputs, PW0024A (TSSOP-24)", Alternate Manufacturer="Texas Instruments", Operating Temperature Range="-40 to 85 C", Rating=Catalog
U15: library part CMP-0080978-2, "3.3-V CAN Transceivers with CAN FD (Flexible Data Rate), D0008A (SOIC-8)", Alternate Manufacturer="Texas Instruments", Alternate PartNumber=TCAN332GD
U16: library part CMP-0073613-3, "4-Channel Ultra-Low-Capacitance IEC ESD Protection Diode, DQA0010A (USON-10)", Alternate Manufacturer="Texas Instruments"
U23: library part CMP-0122273-1, "5-V, 1.85-A boost converter with power good, output discharge and PFM/PWM control 8-SOT-5X3 -40 to 125", Digikey Part Number=296-TPS610333DRLRCT-ND, Manufacturer="Texas Instruments", Max Supply Voltage=5.5V, Min Supply Voltage=1.8V, Mouser Part Number=595-TPS610333DRLR, Nominal Supply Current=20uA, Operating Temperature Range="-40¡ãC to +125¡ãC", Output Voltage=5V, Switching Frequency=2.4MHz
U25: library part CMP-0091939-1, "Linear Voltage Regulator IC Positive Fixed 1 Output 300mA SOT-23-5", Digikey Part Number=296-47851-1-ND, Dropout Voltage=260mV, Manufacturer="Texas Instruments", Max Supply Voltage=5.5V, Min Supply Voltage=2V, Mouser Part Number=595-TLV70333DBVR, Nominal Supply Current=35-370uA, Operating Temperature Range="-40¡ãC to +125¡ãC", Output Voltage=3.3V
U26: library part CMP-0076064-3, "High-Speed, Low-Power, Robust EMC Quad-Channel Digital Isolator, DW0016B (SOIC-16)", Alternate Manufacturer="Texas Instruments", Alternate PartNumber=ISO7741DW, Operating Temperature Range="-55 to 125 C", Rating=Catalog
U27: library part CMP-0078446-2, "High Speed, Robust EMC Triple-Channel Digital Isolators, DW0016B (SOIC-16)", Alternate Manufacturer="Texas Instruments", Alternate PartNumber=ISO7731DW, Operating Temperature Range="-55 to 125 C", Rating=Catalog
USB1: library part CMP-0092137-1, "Connector, USB Type-C 24 pin Mid Mount dual row Receptacle Surface Mount", Manufacturer=MUP, Operating Temperature Range="-25¡ãC to +85¡ãC"
Y1: library part CMP-0004635-3, "Crystal, 16 MHz, 8pF, SMD", Frequency Stability=+/-30ppm, Frequency_Fixed=16MHz, Manufacturer=NDK, Supplier Part Number 1=644-1157-1-ND
Y2: library part CMP-0093781-1, "20 MHz ¡À10ppm Crystal 8pF 50 Ohms 4-SMD, No Lead", Digikey Part Number=1923-830108207209CT-ND, Frequency_Fixed=20MHz, Frequency Stability=20ppm, Frequency Tolerance=10ppm, Load Capacitance=8pF, Manufacturer="Wurth Electronics", Mouser Part Number=710-830108207209, Operating Temperature Range="-40¡ãC to +85¡ãC"
ZZ1: library part CMP-0077236-1
ZZ2: library part CMP-0077237-1
ZZ3: library part CMP-0077238-1

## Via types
v1: diameter 0.559, hole 0.203, Top Signal to Bottom Signal, tented both sides, 833 vias
v2: diameter 0.5, hole 0.2, Top Signal to Bottom Signal, tented both sides, 146 vias
v3: diameter 0.356, hole 0.203, Top Signal to Bottom Signal, tented both sides, 83 vias
v4: diameter 0.4, hole 0.2, Top Signal to Bottom Signal, tented both sides, 2 vias

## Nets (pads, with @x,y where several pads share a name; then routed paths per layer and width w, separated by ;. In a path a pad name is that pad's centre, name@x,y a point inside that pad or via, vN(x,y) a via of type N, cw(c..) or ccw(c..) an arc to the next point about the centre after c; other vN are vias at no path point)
+1V25_MCU: C59.1 C85.1 L1.1 L5.2 R72.2 TP11.1 | length 3.6
  Top Signal w0.254: R72.2@-34.835,99.333 -34.195,99.333 -33.782,99.746 -32.976,99.746 TP11.1@-32.339,100.383 ; v1@-31.453,99.797 v1@-30.945,100.305
  other v1: -31.564,100.051 -30.861,100.051 -31.509,100.678 -30.912,100.736
+3V3_ISO_JTAG: C130.1 C133.1 J101.1 R74.1 R76.1 U4.6 U5.6 U26.10 U26.16 U27.10 U27.16 | length 52.8
  Top Signal w0.305: U26.10@-44.726,115.118 -44.726,117.377 -43.663,118.44 -37.138,118.44 -34.239,118.44 -16.385,118.44 -15.524,117.579 J101.1@-15.524,115.973 ; v1(-39.949,112.314) -39.741,112.522 U4.6@-39.183,112.522 ; v1(-37.138,117.841) -37.138,118.369 -37.067,118.44 ; U26.16@-37.106,115.118 v1@-37.106,117.85 ; -34.233,118.44 -34.239,118.434 v1(-34.239,117.805) -33.609,117.175 U27.10@-33.609,115.118 ; U27.16@-25.989,115.118 -25.989,114.651 -25.989,114.457 -25.705,114.173 -25.705,112.46 -25.494,112.248 U5.6@-25.494,111.933
  Bottom Signal w0.305: v1(-39.949,112.314) -39.741,112.522 -39,112.522 -37.654,113.868 v1(-37.008,113.868) ; v1(-37.138,117.841) -37.096,117.798 R74.1@-37.096,116.967 ; C130.1@-34.241,116.866 -34.241,117.804 v1(-34.239,117.805) ; C133.1@-27.474,116.453 v1(-27.474,117.841) ; R76.1@-26.023,116.983 -26.023,117.952 v1(-26.013,117.962)
+3V3_MCU: C5.2 C12.2 C16.1 C17.2 C18.1 C21.1 C60.1 C64.1 C78.2 C79.1 C83.2 C84.1 C91.1 C119.1 J1/J3.1 J11.10 J17.1 J18.2 JP4.2 JP6.1 JP8.1 L2.1 L3.1 R12.2 R13.2 R14.2 R15.2 R25.2 R28.2 R30.2 R34.2 R44.2 R59.2 R74.2 R76.2 S2.1 S2.4 S3.3 S3.6 S5.3 S5.6 TP4.1 U6.8 U7.5 U8.8 U9.8 U10.19 U11.16 U13.1 U14.16 U15.3 | length 70.2
  Top Signal w0.305: v1(-31.069,109.474) -31.064,109.479 U6.8@-31.064,110.581 ; v1(-29.667,39.345) -29.679,39.357 S5.3@-29.679,40.367 -28.302,40.367 v1(-28.296,40.361) -28.289,40.367 S5.6@-25.979,40.367 ; S2.1@-28.444,103.883 -26.19,103.883 v1(-26.162,103.911) -26.134,103.883 S2.4@-24.744,103.883 ; v1(-27.534,109.474) U9.8@-27.534,110.556 ; R15.2@-20.193,89.722 -19.771,90.145 -15.977,90.145 -15.571,89.739 R14.2@-15.376,89.739 ; U13.1@-19.666,26.089 -19.576,26.179 C21.1@-18.364,26.179 -17.721,26.179 v1(-17.704,26.162) ; v1(-19.339,97.907) -18.745,97.907 R13.2@-18.669,97.831 ; U8.8@-19.086,107.183 -17.39,107.183 v1(-17.374,107.199) ; U7.5@-17.905,89.15 v1@-17.905,90.092 ; v1(-17.101,16.586) U15.3@-17.101,17.889 ; R12.2@-16.993,97.831 -16.907,97.917 -16.856,97.866 v1(-16.332,97.866)
  Top Signal w0.381: v1(-34.163,30.841) U11.16@-32.669,30.841 ; U14.16@-23.652,30.872 -22.363,30.872 v1(-22.352,30.861) ; S3.6@-14.55,75.918 -14.478,75.99 -12.795,75.99 v1(-12.776,75.971) -10.903,75.971 S3.3@-10.85,75.918
  PWR w0.381: J1/J3.1@-52.061,106.7 -50.21,108.551 -50.21,111.4 J18.2@-52.061,113.251
  Bottom Signal w0.152: R28.2@-40.499,109.185 -40.499,109.717 -39.903,110.312 R44.2@-39.71,110.312 ; R44.2@-39.71,110.388 R44.2@-39.71,110.312 ; R25.2@-35.027,109.126 -35.257,109.357 v1(-36.26,109.357) -36.86,109.957 -38.68,109.957 -39.036,110.312 R44.2@-39.71,110.312
  Bottom Signal w0.305: R74.2@-37.096,115.367 -36.41,114.681 v1(-36.043,114.681) ; C12.2@-31.069,108.748 v1(-31.069,109.474) ; C18.1@-27.569,108.864 -27.569,109.439 v1(-27.534,109.474) ; R76.2@-26.023,115.383 -25.848,115.383 -25.119,114.654 v1(-24.709,114.654) ; v1(-25.171,23.698) -25.171,23.774 -24.462,23.774 R30.2@-24.117,24.119 ; v1(-25.146,22.428) R34.2@-24.092,22.428 ; C17.2@-18.085,107.014 -17.9,107.199 v1(-17.374,107.199) ; v1(-17.907,90.094) C16.1@-17.907,90.815 ; C5.2@-17.117,15.875 -17.117,16.57 v1(-17.101,16.586)
  Bottom Signal w0.381: JP8.1@-52.061,50.82 -52.057,50.824 -52.057,53.696 ; v1(-13.513,10.902) -13.465,10.902 -13.408,10.845 -11.468,10.845 -11.455,10.858 ; C78.2@-11.455,73.824 -10.008,73.824 C79.1@-9.855,73.978 -9.823,73.946 -9.049,73.946 v1(-9.017,73.914) ; -11.442,10.845 C84.1@-10.567,10.845 ; v1(-10.617,9.982) -10.617,10.03 -10.562,10.085 -10.562,10.701 -10.537,10.726 -10.283,10.726 C84.1@-10.567,11.011 ; C84.1@-10.283,10.845 -7.392,10.845 JP6.1@-7.188,11.049 ; v1@-8.999,73.896 -8.48,73.896 -8.43,73.946 v1(-8.382,73.946) -8.334,73.946 -8.277,73.889 -6.55,73.889 JP4.2@-6.341,73.68 ; v1(-8.534,65.278) -8.505,65.307 -7.806,65.307 -7.696,65.417 R59.2@-7.696,65.472
  other v1: -31.598,22.667 -32.258,22.694 -32.258,23.317 -31.572,23.343 -34.849,38.786 -34.087,38.786 -34.849,39.37 -34.087,39.37 -48.539,53.504 -47.909,53.504 -48.539,54.254 -47.909,54.254 -27.22,103.879 -45.974,116.992 -46.025,117.577
+3V3_PMIC: C87.2 C88.2 J18.1 U10.1
+3V3_XDS110: C126.1 C129.1 C132.1 C134.2 C135.2 C136.2 C137.2 C138.2 C139.1 C140.1 C141.2 R16.2 R96.1 R101.2 R102.2 R103.2 R104.2 R174.2 R177.2 U2.7 U2.8 U2.9 U2.16 U2.26 U2.28 U2.39 U2.47 U2.51 U2.52 U2.69 U2.79 U2.90 U2.101 U2.113 U2.122 U25.5 U26.1 U26.7 U27.1 U27.7 | length 38.3
  Top Signal w0.254: U26.7@-44.726,124.868 -44.726,123.511 v1(-44.654,123.439) ; U25.5@-37.764,132.79 -37.65,132.675 v1(-37.65,131.943) ; v1(-37.138,127.611) -37.106,127.578 U26.1@-37.106,124.868 ; v1(-36.565,133.459) -36.419,133.313 C126.1@-36.419,132.414 ; R96.1@-35.173,132.389 v1(-35.173,133.459) ; U27.7@-33.609,124.868 -33.609,123.704 v1(-33.585,123.68) ; U27.1@-25.989,124.868 -25.945,124.824 v1(-25.115,124.824) ; U2.28@-22.926,128.135 v1(-21.944,128.135) ; U2.26@-22.926,128.935 v1(-21.944,128.935) ; U2.39@-19.026,125.035 v1(-19.026,126.017) ; U2.122@-19.026,140.435 -19.026,139.712 -18.658,139.343 v1(-18.658,139.261) ; v1(-18.292,122.05) R16.2@-17.53,122.05 ; v1(-16.226,126.344) -15.826,125.944 U2.47@-15.826,125.035 ; U2.113@-15.426,140.435 -15.426,139.471 v1(-15.153,139.198) ; U2.51@-14.226,125.035 -14.226,125.872 v1(-14.027,126.07) -13.826,125.869 U2.52@-13.826,125.035 ; v1(-11.864,121.361) -11.863,121.362 R104.2@-11.863,122.095 R104.2@-11.863,122.168 ; v1(-10.626,139.453) U2.101@-10.626,140.435 ; R103.2@-10.615,122.102 -10.578,122.14 v1(-9.806,122.14) ; v1@-8.543,132.128 U2.79@-7.52,132.128 ; v1(-8.508,136.535) U2.90@-7.526,136.535 ; U2.69@-7.526,128.135 -6.149,128.135 v1(-6.097,128.083) -6,128.083 R174.2@-5.267,127.35 ; R102.2@-6.651,122 -6.648,121.997 v1(-5.79,121.997) ; R101.2@-6.651,123.263 v1(-5.765,123.263) ; R177.2@-5.267,125.876 -5.141,126.002 v1(-4.506,126.002)
  Bottom Signal w0.254: C132.1@-26.062,124.868 -26.018,124.824 v1(-25.115,124.824) ; v1(-21.944,128.135) -21.583,128.496 -21.562,128.496 -21.562,128.553 v1(-21.944,128.935) ; v1(-21.324,134.002) -21.318,134.008 -21.318,134.768 -21.324,134.773 -21.312,134.785 -21.312,136.067 -21.289,136.09 v1(-21.289,136.935) ; C135.2@-19.295,138.851 -19.067,138.851 v1(-18.658,139.261) ; v1(-16.226,126.344) -16.168,126.286 -16.168,125.619 C137.2@-16.052,125.503 ; v1(-15.153,139.198) -14.699,138.744 C134.2@-14.374,138.744 ; C139.1@-9.155,131.732 -8.752,132.135 -8.729,132.112 v1(-8.572,132.112)
  Bottom Signal w0.3: C136.2@-14.073,125.503 -14.04,125.536 -14.04,126.058 v1(-14.027,126.07)
+5V0_MCU: C22.1 C23.1 C76.2 C77.1 C81.2 C82.1 C86.2 C92.1 C93.1 C94.1 C107.2 C120.1 C121.1 J1/J3.21 J12.4 J13.4 J15.1 J15.6 JP1.2 JP5.1 JP7.1 JP8.2 R5.2 R6.2 R7.2 R8.2 R9.2 R10.2 R23.2 R24.1 R82.2 TP5.1 U10.9 U10.14 U10.24 U13.23 U13.24 U23.8 | length 67.6
  Top Signal w0.254: C120.1@-46.016,12.12 C120.1@-45.999,12.103 -45.682,11.786 -45.308,11.786 -44.774,11.252 U23.8@-43.581,11.252 ; R23.2@-43.088,6.883 v1(-42.342,6.883) R24.1@-41.596,6.883 ; v1(-40.849,103.302) -40.813,103.338 C92.1@-39.878,103.338 -39.362,103.854 U10.9@-39.362,104.547 ; U10.24@-39.862,107.847 -39.862,108.195 ; v1@-39.213,109.587 -39.173,109.626 v1(-39.123,109.626) ; U10.14@-37.212,105.197 -36.887,105.197 ; C94.1@-36.307,102.895 C94.1@-36.316,102.904 ; C93.1@-36.282,101.168 C93.1@-36.333,101.219 ; v1(-33.909,108.61) -33.871,108.572 C107.2@-33.871,107.594 C107.2@-33.871,107.239 ; U13.23@-20.316,20.189 -20.316,21.136 -20.015,21.438 v1(-19.941,21.438) -19.685,21.182 -19.685,20.208 U13.24@-19.666,20.189 ; -39.862,108.195 -39.862,109.571 C86.2@-39.878,109.587 -40.023,109.441 -40.023,108.356 -39.862,108.195 ; -36.887,105.197 -36.625,105.197 -36.474,105.047 ; -36.887,105.197 -36.637,104.947 -36.637,101.524 C93.1@-36.519,101.406 ; -36.637,100.609 -36.637,100.273 -36.567,100.203 -36.413,100.357 v1(-36.413,100.381) ; -36.637,100.609 -36.637,100.914 C93.1@-36.383,101.168 ; -36.637,100.609 -36.614,100.586 v1@-36.383,100.586 ; C93.1@-36.519,101.406 C93.1@-36.333,101.219 ; C93.1@-36.519,101.406 -36.383,101.541 -36.383,102.895 C94.1@-36.316,102.828 ; -36.474,105.047 -36.316,104.888 C94.1@-36.316,102.904 ; -36.474,105.047 -36.474,103.063 C94.1@-36.316,102.904 ; v1(-36.413,100.381) -36.275,100.381 -36.157,100.499 -36.157,102.669 C94.1@-36.316,102.828 ; v1(-36.413,100.381) -36.383,100.411 v1@-36.383,100.586 ; v1@-36.383,100.586 C93.1@-36.383,101.168 ; C93.1@-36.383,101.168 C93.1@-36.333,101.219 ; C93.1@-36.333,101.219 -36.316,101.235 C94.1@-36.316,102.828 ; C94.1@-36.316,102.828 C94.1@-36.316,102.904
  Top Signal w0.381: v1(-54.94,116.357) -54.873,116.425 JP1.2@-53.944,116.425 ; v1(-54.864,117.467) -54.797,117.535 JP1.2@-53.891,117.535 ; v1(-53.696,114.833) -53.681,114.833 JP1.2@-53.681,116.717 ; C121.1@-47.6,12.103 C121.1@-47.473,11.976 ; v1(-47.523,11.151) -47.545,11.172 C121.1@-47.545,11.862 ; v1(-46.05,11.125) -46.076,11.151 -46.076,11.862 C121.1@-47.358,11.862 ; C120.1@-46.016,12.12 R82.2@-49.042,12.12 -48.784,11.862 C121.1@-47.545,11.862 ; C86.2@-39.807,109.626 v1@-39.173,109.626 ; v1(-30.139,8.979) -30.124,8.994 R10.2@-30.124,9.792 ; v1@-28.042,9.093 R9.2@-28.042,9.763 ; v1(-26.568,9.068) R8.2@-26.568,9.792 ; v1(-24.562,8.057) R7.2@-24.562,8.9 ; v1(-23.089,8.077) R6.2@-23.089,8.839 ; v1(-21.869,8.026) -21.784,8.112 R5.2@-21.784,8.979 ; C121.1@-47.545,11.862 -47.545,11.904 C121.1@-47.473,11.976 ; C121.1@-47.545,11.862 C121.1@-47.358,11.862 ; C121.1@-47.473,11.976 C121.1@-47.358,11.862
  PWR w0.381: -40.923,109.929 -39.426,109.929 v1(-39.123,109.626)
  Bottom Signal w0.254: C23.1@-20.152,20.523 C23.1@-20.077,20.598 ; v1(-19.941,21.438) -19.941,21.355 -20.077,21.219 C23.1@-20.077,20.598 ; v1(-18.974,21.36) -18.974,20.666 -19.04,20.599 -20.076,20.599 C23.1@-20.077,20.598
  Bottom Signal w0.381: JP7.1@-52.061,10.18 -51.922,10.041 -49.632,10.041 ; JP5.1@-52.061,73.68 -48.701,73.68 -48.595,73.574 C77.1@-48.595,73.546 v1(-48.595,72.466) ; -49.784,10.05 C82.1@-48.768,10.05 ; v1(-48.717,11.1) -48.743,11.074 -48.743,10.274 C82.1@-48.768,10.249 C82.1@-48.768,10.05 ; C81.2@-47.193,10.021 -47.143,10.021 C81.2@-47.118,10.046 ; v1@-46.99,72.441 -46.99,73.8 C76.2@-46.936,73.854 ; v1(-46.66,10.668) -46.694,10.634 -46.694,10.47 C81.2@-47.118,10.046 ; C82.1@-48.768,10.05 -48.764,10.046 C81.2@-47.118,10.046
  other v1: -28.067,9.068 -47.015,72.441
+5V0_USB: C80.2 C127.1 C128.1 JP1.1 R68.2 R69.2 R164.1 U25.1 U25.3 USB1.A4 USB1.A9 USB1.B4 USB1.B9 | length 17.8
  Top Signal w0.3: v1(-7.865,141.794) -7.824,141.794 -7.625,141.595 -7.136,141.595 -6.986,141.445 R164.1@-6.986,141.345
  Top Signal w0.381: v1(-54.671,131.208) -54.658,131.221 -53.073,131.221 R69.2@-53.061,131.233 ; v1(-48.361,132.658) -48.361,133.379 C80.2@-48.385,133.403 -48.385,135.189 v1(-48.02,135.554) -47.586,135.988 -47.586,137.498 -47.336,137.748 USB1.B4@-47.336,138.185 ; USB1.B9@-44.836,138.185 -44.836,137.354 -45.086,137.104 -45.086,136.093 v1@-44.525,135.531 ; v1(-43.691,132.757) -43.657,132.791 -42.697,132.791 C127.1@-42.588,132.901 ; v1(-42.857,130.754) C128.1@-41.706,130.754 ; C127.1@-42.588,132.944 C127.1@-42.588,132.901 ; C128.1@-41.706,130.748 -41.706,130.78 -41.596,130.89 U25.3@-40.364,130.89 ; U25.1@-40.364,132.79 -40.366,132.792 -42.478,132.792 C127.1@-42.588,132.902
  other v1: -56.176,123.439 -54.855,123.473 -56.277,124.489 -54.931,124.591 -53.737,125.835 -43.751,131.649 -41.675,131.821 -40.836,133.826 -44.552,135.56
ADC_VREF: C15.1 U3.6 U12.3 U12.5 | length 11.1
  Top Signal w0.305: U12.5@-42.382,51.87 -40.943,51.87 -40.293,51.22 -40.091,51.22 ; U3.6@-41.935,46.177 -41.026,46.177 -40.091,47.112 -40.091,48.336 -40.091,51.22 ; U12.3@-37.932,51.22 -40.091,51.22
ADCINA0/DACA_OUT: J1/J3.30 R37.1 | length 4
  Top Signal w0.127: J1/J3.30@-49.521,83.84 -49.517,83.844 R37.1@-45.534,83.844
ADCINA1: J1/J3.2 R38.1 | length 7.4
  Top Signal w0.127: J1/J3.2@-52.061,104.16 -51.607,104.16 -50.343,102.895 -46.287,102.895 -45.583,102.191 R38.1@-45.432,102.191
ADCINA2: J1/J3.6 R39.1 | length 7.4
  Top Signal w0.127: J1/J3.6@-52.061,94 -50.778,92.718 -47.226,92.718 -46.507,91.998 R39.1@-45.534,91.998
ADCINA3: J1/J3.24 R40.1 | length 4.4
  Top Signal w0.127: J1/J3.24@-49.521,99.08 -46.781,99.08 -45.815,98.114 R40.1@-45.534,98.114
ADCINA4A5_N: J10.3 R42.1 | length 14.3
  Top Signal w0.152: J10.3@-52.061,66.06 -52.061,66.951 -52.192,67.081 -53.696,67.081 -54.253,67.638 -54.253,70.055 -52.705,71.603 -51.71,71.603 -49.348,73.965 -48.145,73.965 R42.1@-47.615,74.495
ADCINA4A5_P: J10.1 R41.1 | length 13.4
  Top Signal w0.152: J10.1@-52.061,68.6 -52.061,67.577 -52.277,67.361 -53.543,67.361 -53.973,67.791 -53.973,69.939 -52.589,71.323 -51.594,71.323 -49.282,73.635 -47.831,73.635 R41.1@-47.565,73.368
ADCINA6: J5/J7.64 R43.1 | length 4.5
  Top Signal w0.127: J5/J7.64@-49.521,35.58 -46.714,35.58 R43.1@-45.523,34.389
ADCINA7: J1/J3.28 R45.1 | length 4.4
  Top Signal w0.127: J1/J3.28@-49.521,88.92 -48.522,87.921 R45.1@-45.534,87.921
ADCINA14/B14/C14/D14/E14: J1/J3.23 R46.1 | length 4.6
  Top Signal w0.127: J1/J3.23@-49.521,101.62 -47.035,101.62 -45.568,100.152 R46.1@-45.534,100.152
ADCINA15/B15/C15/D15/E15: J5/J7.63 R47.1 | length 4.7
  Top Signal w0.127: J5/J7.63@-49.521,38.12 -47.234,38.12 R47.1@-45.523,36.41
ADCINB2B3_N: J10.4 R49.1 | length 10
  Top Signal w0.152: J10.4@-49.521,66.06 -49.483,66.098 -49.483,66.951 -49.65,67.118 -50.524,67.118 -50.876,67.471 -50.876,69.647 -50.317,70.206 -48.218,70.206 -47.761,69.748 -46.736,69.748 -46.33,70.155 R49.1@-46.193,70.155
ADCINB2B3_P: J10.2 R48.1 | length 9
  Top Signal w0.152: J10.2@-49.521,68.6 -49.521,67.6 -49.698,67.424 -50.296,67.424 -50.597,67.724 -50.597,69.527 -50.223,69.901 -48.309,69.901 -47.877,69.469 -46.599,69.469 R48.1@-46.193,69.063
ADCINB4: J1/J3.27 R50.1 | length 4.6
  Top Signal w0.127: J1/J3.27@-49.521,91.46 -48.021,89.96 R50.1@-45.534,89.96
